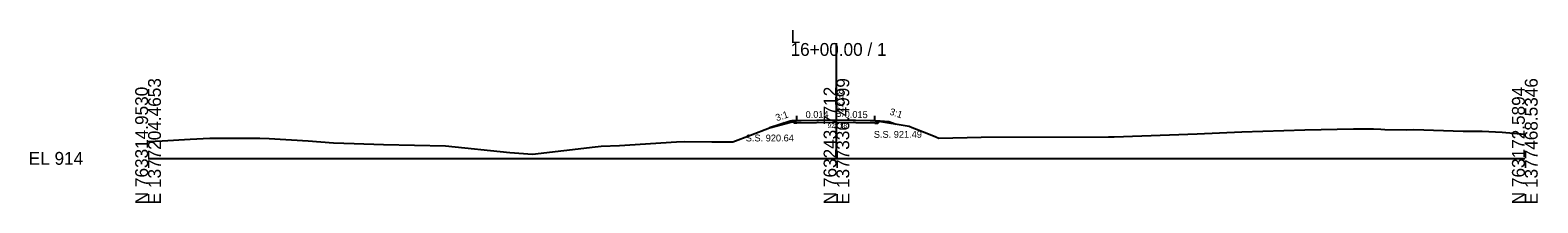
# Model space of a CAD drawing. Extents: x -26 to 303, y -10 to 6523.
# Drawn here: x -25.7 to 302.8, y 5990.3 to 6027.9 of the extents above; entities that cross this region are included whole.
import ezdxf

# ---------------------------------------------------------------- set-up
doc = ezdxf.new("R2010")
doc.units = 0
for name, color, linetype in [('Exist Cross Section Cell', 7, 'Continuous'), ('Exist XS Center Line Elevation Label', 7, 'Continuous'), ('Exist XS Ground Line', 7, 'Continuous'), ('Prop XS Dump Level', 7, 'Continuous'), ('Prop XS Elevation Labels', 7, 'Continuous'), ('Prop XS EOT Tick Mark', 7, 'Continuous'), ('Prop XS Finish Grade', 7, 'Continuous'), ('Prop XS Finish Grade Earthwork', 7, 'Continuous'), ('Prop XS Finish Grade Pavement', 7, 'Continuous'), ('Prop XS Pvmt Edge Slope', 7, 'Continuous'), ('Prop XS SE Text', 7, 'Continuous'), ('Prop XS Side Slope Text', 7, 'Continuous'), ('Prop XS SS Elevation Text', 7, 'Continuous'), ('Prop XS Subgrade Earthwork', 7, 'Continuous')]:
    doc.layers.add(name, color=color, linetype=linetype)

msp = doc.modelspace()

# ---------------------------------------------------------------- linework, layer by layer
at = {"layer": 'Exist Cross Section Cell'}
for p, q in [((150, 6000), (150, 6025.14)), ((0, 6000), (150, 6000)), ((150, 6000), (300, 6000))]:
    msp.add_line(p, q, dxfattribs=at)
at = {"layer": 'Exist XS Ground Line'}
for p, q in [((131.3, 6005.06), (135.42, 6006.64)), ((135.42, 6006.64), (137.86, 6007.31)), ((137.86, 6007.31), (140.03, 6007.87)), ((140.03, 6007.87), (141.38, 6008.26)), ((141.38, 6008.26), (142.34, 6008.27)), ((142.34, 6008.27), (149.9, 6008.38)), ((149.9, 6008.38), (157.37, 6008.27)), ((157.37, 6008.27), (158.4, 6008.26)), ((158.4, 6008.26), (165.84, 6007.01)), ((165.84, 6007.01), (166.47, 6006.75)), ((166.47, 6006.75), (169.68, 6005.48)), ((228.6, 6005.37), (238.35, 6005.79)), ((238.35, 6005.79), (252.07, 6006.24)), ((252.07, 6006.24), (262.64, 6006.47)), ((262.64, 6006.47), (267, 6006.44)), ((267, 6006.44), (268.59, 6006.39)), ((268.59, 6006.39), (269.49, 6006.32)), ((269.49, 6006.32), (274.19, 6006.24)), ((274.19, 6006.24), (275.82, 6006.3)), ((275.82, 6006.3), (286.57, 6005.96)), ((286.57, 6005.96), (288.31, 6005.93)), ((288.31, 6005.93), (290.7, 6005.9)), ((290.7, 6005.9), (295.07, 6005.69)), ((295.07, 6005.69), (300, 6005.31)), ((0, 6003.7), (3.08, 6003.82)), ((3.08, 6003.82), (9.16, 6004.22)), ((9.16, 6004.22), (13.49, 6004.37)), ((13.49, 6004.37), (24.35, 6004.41)), ((24.35, 6004.41), (26.42, 6004.34)), ((26.42, 6004.34), (34.88, 6003.79)), ((34.88, 6003.79), (40.39, 6003.4)), ((40.39, 6003.4), (44.94, 6003.26)), ((44.94, 6003.26), (51.3, 6003)), ((51.3, 6003), (64.79, 6002.75)), ((64.79, 6002.75), (78.83, 6001.3)), ((83.74, 6000.95), (97.46, 6002.52)), ((97.46, 6002.52), (98.76, 6002.63)), ((98.76, 6002.63), (102.74, 6002.81)), ((102.74, 6002.81), (115.18, 6003.62)), ((115.18, 6003.62), (116.82, 6003.71)), ((116.82, 6003.71), (122.85, 6003.61)), ((122.85, 6003.61), (127.39, 6003.61)), ((127.39, 6003.61), (131.3, 6005.06)), ((169.68, 6005.48), (171.63, 6004.7)), ((171.63, 6004.7), (172.34, 6004.42)), ((172.34, 6004.42), (181.55, 6004.6)), ((181.55, 6004.6), (209.3, 6004.68)), ((209.3, 6004.68), (209.95, 6004.67)), ((209.95, 6004.67), (210.5, 6004.69)), ((210.5, 6004.69), (228.6, 6005.37)), ((78.83, 6001.3), (83.74, 6000.95))]:
    msp.add_line(p, q, dxfattribs=at)
at = {"layer": 'Prop XS Dump Level'}
for p, q in [((141.37, 6008.26), (150, 6008.38)), ((150, 6008.38), (158.4, 6008.26))]:
    msp.add_line(p, q, dxfattribs=at)
at = {"layer": 'Prop XS EOT Tick Mark'}
for p, q in [((141.38, 6008.26), (141.38, 6009.26)), ((158.4, 6008.26), (158.4, 6009.26))]:
    msp.add_line(p, q, dxfattribs=at)
at = {"layer": 'Prop XS Finish Grade'}
for p, q in [((141.38, 6008.26), (140.27, 6008.17)), ((158.4, 6008.26), (159.5, 6008.17))]:
    msp.add_line(p, q, dxfattribs=at)
at = {"layer": 'Prop XS Finish Grade Earthwork'}
for p, q in [((139.92, 6008.14), (135.42, 6006.64)), ((140.27, 6008.17), (139.92, 6008.14)), ((159.5, 6008.17), (161.4, 6008.02)), ((161.4, 6008.02), (162.99, 6007.48))]:
    msp.add_line(p, q, dxfattribs=at)
at = {"layer": 'Prop XS Finish Grade Pavement'}
for p, q in [((141.37, 6008.26), (150, 6008.38)), ((150, 6008.38), (158.4, 6008.26))]:
    msp.add_line(p, q, dxfattribs=at)
at = {"layer": 'Prop XS Pvmt Edge Slope'}
for p, q in [((141.37, 6008.26), (140.78, 6007.66)), ((158.4, 6008.26), (158.99, 6007.66))]:
    msp.add_line(p, q, dxfattribs=at)
at = {"layer": 'Prop XS Subgrade Earthwork'}
for p, q in [((140.78, 6007.66), (140.27, 6008.17)), ((141.37, 6007.67), (140.78, 6007.66)), ((150, 6007.8), (141.37, 6007.67)), ((158.4, 6007.67), (150, 6007.8)), ((158.4, 6007.67), (158.99, 6007.66)), ((158.99, 6007.66), (159.5, 6008.17))]:
    msp.add_line(p, q, dxfattribs=at)

# ---------------------------------------------------------------- texts
at = {"layer": 'Exist Cross Section Cell'}
for s, p in [('16+00.00 / 1', (140, 6022.34)), ('L', (140, 6025.14)), ('EL 914', (-26, 5998.6))]:
    msp.add_text(s, height=2.8, dxfattribs=at).set_placement(p)
for s, p in [('N 763314.9530', (0, 5990)), ('E 1377204.4653', (2.8, 5990)), ('E 1377336.4999', (152.8, 5990)), ('N 763172.5894', (300, 5990)), ('E 1377468.5346', (302.8, 5990)), ('N 763243.7712', (150, 5990))]:
    msp.add_text(s, height=2.8, rotation=90, dxfattribs=at).set_placement(p)
at = {"layer": 'Exist XS Center Line Elevation Label'}
msp.add_text('922.38', height=0.998, dxfattribs=at).set_placement((148.09, 6006.62))
at = {"layer": 'Prop XS Dump Level'}
for p in [(138.38, 6007.93), (161.4, 6007.93)]:
    msp.add_text('Case1', height=0.04, dxfattribs=at).set_placement(p)
at = {"layer": 'Prop XS Elevation Labels'}
msp.add_text(' 922.38', height=1.5, rotation=90, dxfattribs=at).set_placement((151.5, 6008.38))
at = {"layer": 'Prop XS SE Text'}
for s, rotation, p in [('0.014', 0.807, (143.29, 6008.79)), ('0.015', 359.0456, (151.78, 6008.85))]:
    msp.add_text(s, height=1.5, rotation=rotation, dxfattribs=at).set_placement(p)
at = {"layer": 'Prop XS Side Slope Text'}
for rotation, p in [(18.4349, (137.01, 6008.08)), (341.5651, (161.45, 6009.58))]:
    msp.add_text('3:1', height=1.5, rotation=rotation, dxfattribs=at).set_placement(p)
at = {"layer": 'Prop XS SS Elevation Text'}
for s, p in [('S.S. 921.49', (158.14, 6004.48)), ('S.S. 920.64', (130.24, 6003.69))]:
    msp.add_text(s, height=1.5, dxfattribs=at).set_placement(p)

doc.saveas('drawing.dxf')
